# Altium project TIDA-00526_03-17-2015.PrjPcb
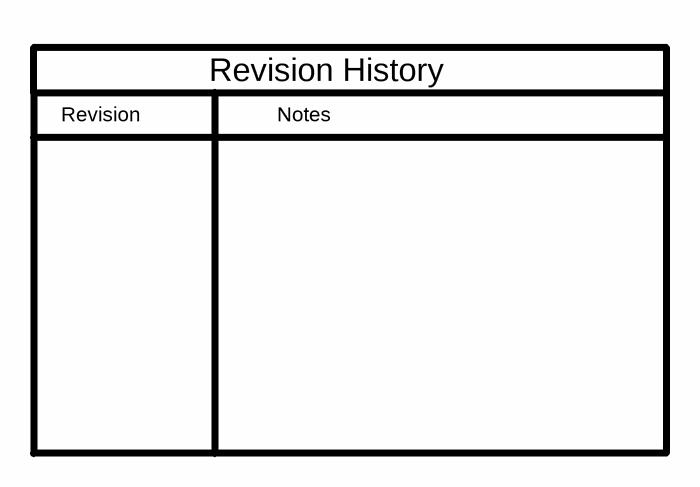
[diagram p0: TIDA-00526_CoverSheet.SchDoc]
TID: 00526; TechSupport: http://www.ti.com/support; SCH_Rev: E1; PRJ_Title: Using LDO for LED control & brightness matching; PRJ_Number: TIDA-00526; PRJ_Engineer: Antony Carvajales; PRJ_Customer: Public Release; PCB_Rev: E1; PCB_Layout: Antony Carvajales; EVM_Orderable: N/A; CopyrightYear: 2015
3 sheets, 39 parts. Net scope: global (net labels, ports and power ports of the same name join across sheets).
Board file: TIDA-00526_TID.PcbDoc
Sheets:
  TIDA-00526_CoverSheet.SchDoc
  TIDA-00526_BlankSheet.SchDoc
  TIDA-00526_Hardware.SchDoc

## Sheet TIDA-00526_CoverSheet.SchDoc
size 431 x 279 mm; Date: Not shown in title block; ApprovedBy: Not shown in title block; CheckedBy: Not shown in title block; Author: Not shown in title block; CompanyName: Not shown in title block; Engineer: Not shown in title block; Organization: Not shown in title block; Address1: Not shown in title block; Address2: Not shown in title block; Address3: Not shown in title block; Address4: Not shown in title block; DocumentNumber: 1; Revision: Use project parameter SCH_Rev; SheetNumber: 1; SheetTotal: 3; PageSetup: Record=PageOptions¦CenterHorizontal=True¦CenterVertical=True¦PrintScale=1.00¦XCorrection=1.00¦YCorrection=1.00¦PrintKind=0¦BorderSize=5000000¦LeftOffset=0¦BottomOffset=0¦Orientation=2¦PaperLength=1000¦PaperWidth=1000¦Scale=100¦PaperSource=15¦PrintQuality=600¦MediaType=1¦DitherType=10¦PaperKind=Letter¦PrintScaleMode=1

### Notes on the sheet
- Revision
- Notes
- Revision History

## Sheet TIDA-00526_BlankSheet.SchDoc
size 431 x 279 mm; Date: Not shown in title block; ApprovedBy: Not shown in title block; CheckedBy: Not shown in title block; Author: Not shown in title block; CompanyName: Texas Instruments; Engineer: Antony Carvajales; Organization: MDP_RF; Address1: Not shown in title block; Address2: Not shown in title block; Address3: Not shown in title block; Address4: Not shown in title block; DocumentNumber: 1; Revision: Use project parameter SCH_Rev; SheetNumber: 2; SheetTotal: 3; PageSetup: Record=PageOptions¦CenterHorizontal=True¦CenterVertical=True¦PrintScale=1.00¦XCorrection=1.00¦YCorrection=1.00¦PrintKind=0¦BorderSize=5000000¦LeftOffset=0¦BottomOffset=0¦Orientation=2¦PaperLength=1000¦PaperWidth=1000¦Scale=100¦PaperSource=15¦PrintQuality=-3¦MediaType=1¦DitherType=10¦PrintScaleMode=1¦PaperKind=Letter¦PaperIndex=1
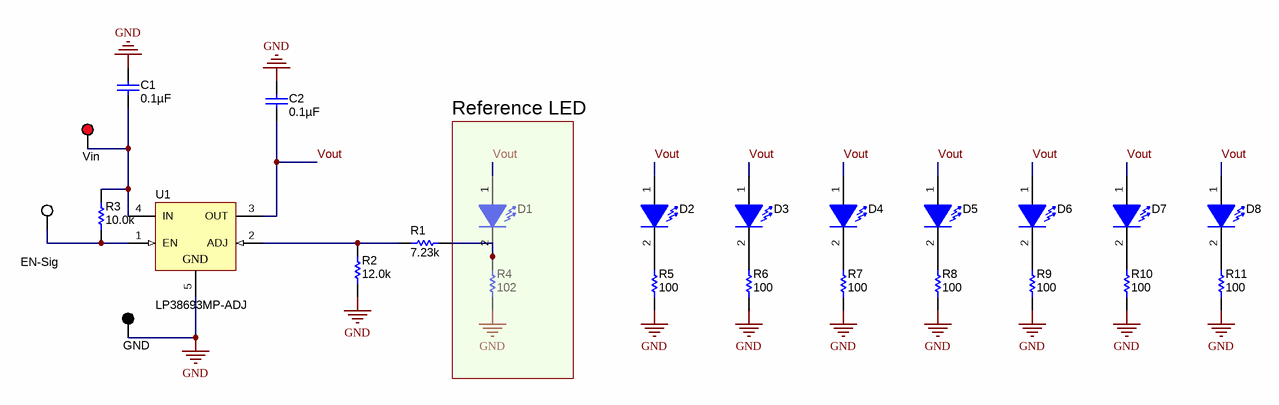
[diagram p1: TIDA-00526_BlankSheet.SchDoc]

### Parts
C1  ValueDisplayed: 0.1µF  [0805_HV]  (hidden comment: C0805C104K3RACTU)
C2  ValueDisplayed: 0.1µF  [0805_HV]  (hidden comment: C0805C104K3RACTU)
D1  C503D-WAN-CCBDB232  [HLMP-341_YELLOW]  (value not drawn)
D2  C503D-WAN-CCBDB232  [HLMP-341_YELLOW]  (value not drawn)
D3  LED, White, TH  [HLMP-341_YELLOW]  (value not drawn)
D4  C503D-WAN-CCBDB232  [HLMP-341_YELLOW]  (value not drawn)
D5  C503D-WAN-CCBDB232  [HLMP-341_YELLOW]  (value not drawn)
D6  C503D-WAN-CCBDB232  [HLMP-341_YELLOW]  (value not drawn)
D7  C503D-WAN-CCBDB232  [HLMP-341_YELLOW]  (value not drawn)
D8  C503D-WAN-CCBDB232  [HLMP-341_YELLOW]  (value not drawn)
EN-Sig  5002  [Keystone5002]  (value not drawn)
GND  5001  [Keystone5001]  (value not drawn)
R1  ValueDisplayed: 7.23k  [0603]  (hidden comment: RT0603DRE077K23L)
R2  ValueDisplayed: 12.0k  [0603]  (hidden comment: RC0603FR-0712KL)
R3  ValueDisplayed: 10.0k  [0603]  (hidden comment: CRCW060310K0FKEA)
R4  ValueDisplayed: 102  [0603]  (hidden comment: CRCW0603102RFKEA)
R5  ValueDisplayed: 100  [0603]  (hidden comment: RC0603FR-07100RL)
R6  ValueDisplayed: 100  [0603]  (hidden comment: RC0603FR-07100RL)
R7  ValueDisplayed: 100  [0603]  (hidden comment: RC0603FR-07100RL)
R8  ValueDisplayed: 100  [0603]  (hidden comment: RC0603FR-07100RL)
R9  ValueDisplayed: 100  [0603]  (hidden comment: RC0603FR-07100RL)
R10  ValueDisplayed: 100  [0603]  (hidden comment: RC0603FR-07100RL)
R11  ValueDisplayed: 100  [0603]  (hidden comment: RC0603FR-07100RL)
U1  LP38693MP-ADJ  [MP05A_N]
Vin  5000  [Keystone5000]  (value not drawn)

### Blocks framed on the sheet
Reference LED: D1 R4

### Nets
GND: C1.1 C2.1 GND.1 R2.1 R4.1 R5.1 R6.1 R7.1 R8.1 R9.1 R10.1 R11.1 U1.5(GND)
Vout: C2.2 D1.1(A) D2.1(A) D3.1(A) D4.1(A) D5.1(A) D6.1(A) D7.1(A) D8.1(A) U1.3(OUT)
NetC1_2: C1.2 R3.2 U1.4(IN) Vin.1
NetD1_2: D1.2(K) R1.2 R4.2
NetD2_2: D2.2(K) R5.2
NetD3_2: D3.2(K) R6.2
NetD4_2: D4.2(K) R7.2
NetD5_2: D5.2(K) R8.2
NetD6_2: D6.2(K) R9.2
NetD7_2: D7.2(K) R10.2
NetD8_2: D8.2(K) R11.2
NetEN-Sig_1: EN-Sig.1 R3.1 U1.1(EN)
NetR1_1: R1.1 R2.2 U1.2(ADJ)

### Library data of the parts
C1 C2 = C0805C104K3RACTU: CAP, CERM, 0.1 µF, 25 V, +/- 10%, X7R, 0805; Manufacturer: Kemet; Polarized: N; CompType: Capacitor; Value: 0.1uF; U/M: EA; Cap_F: 0.0000001; Tolerance_%: 10; ESR_ohm: 0.064; Value1: 0.064 ohm; VDC_V: 25; Value2: 25V; IRMS_A: 1.64; TaMin_C: -55; TaMax_C: 125; Cap_Case: 0805
D1 D2 D4 D5 D7 D8 = HLMP-3416: LED, White, TH; Manufacturer: CREE
D3 = HLMP-3416: Manufacturer: CREE; PartNumber: C503D-WAN-CCBDB232
D6 = HLMP-3416: LED, white, TH; Manufacturer: CREE
EN-Sig = 5002: Test Point, Miniature, White, TH; Manufacturer: Keystone; CompType: Test Point Loop; U/M: EA
GND = 5001: Test Point, Miniature, Black, TH; Manufacturer: Keystone; CompType: Test Point Loop; U/M: EA
R1 = RT0603DRE077K23L: RES, 7.23 k, 0.5%, 0.1 W, 0603; Manufacturer: Yageo America; CompType: Resistor; Value: 7.23k; Res_ohm: 7230; Value_Code: 7k23; Tolerance_%: 0.5; Power_W: 0.1; Value2: 0.1W; VDC_V: 75; TempCo: 50 ppm/C; EIA_Code: E192; U/M: EA
R2 = RC0603FR-0712KL: RES, 12.0 k, 1%, 0.1 W, 0603; Manufacturer: Yageo America; CompType: Resistor; Value: 12.0k; Res_ohm: 12000; Value_Code: 12k0; Tolerance_%: 1; Power_W: 0.1; Value2: 0.1W; VDC_V: 150; TempCo: 200 ppm/C; U/M: EA
R3 = CRCW060310K0FKEA: RES, 10.0 k, 1%, 0.1 W, 0603; Manufacturer: Vishay-Dale; CompType: Resistor; Value: 10.0k; Res_ohm: 10000; Value_Code: 10k0; Tolerance_%: 1; Power_W: 0.1; Value2: 0.1W; VDC_V: 75; TempCo: 100 ppm/C; EIA_Code: E96; U/M: EA
R4 = CRCW0603102RFKEA: RES, 102, 1%, 0.1 W, 0603; Manufacturer: Vishay-Dale; CompType: Resistor; Value: 102; Value_Code: 102R; Tolerance_%: 1; Power_W: 0.1; Value2: 0.1W; VDC_V: 75; TempCo: 100 ppm/C; EIA_Code: E96; U/M: EA
R5-R11 = RC0603FR-07100RL: RES, 100, 1%, 0.1 W, 0603; Manufacturer: Yageo America; CompType: Resistor; Value: 100; Value_Code: 100R; Tolerance_%: 1; Power_W: 0.1; Value2: 0.1W; VDC_V: 150; TempCo: 200 ppm/C; EIA_Code: E96; U/M: EA
U1 = LP38693MP-ADJ: 500mA Low Dropout CMOS Linear Regulators, 5-pin SOT-223; Manufacturer: Texas Instruments; PackageTopMarking: XYTT*LJUB; PowerWise: Y; CompType: LDO IC
Vin = 5000: Test Point, Miniature, Red, TH; Manufacturer: Keystone; CompType: Test Point Loop; U/M: EA

## Sheet TIDA-00526_Hardware.SchDoc
size 431 x 279 mm; Date: Not shown in title block; ApprovedBy: Not shown in title block; CheckedBy: Not shown in title block; Author: Not shown in title block; CompanyName: Not shown in title block; Engineer: Not shown in title block; Organization: Not shown in title block; Address1: Not shown in title block; Address2: Not shown in title block; Address3: Not shown in title block; Address4: Not shown in title block; DocumentNumber: 1; Revision: Use project parameter SCH_Rev; SheetNumber: 3; SheetTotal: 3; PageSetup: Record=PageOptions¦CenterHorizontal=True¦CenterVertical=True¦PrintScale=1.00¦XCorrection=1.00¦YCorrection=1.00¦PrintKind=0¦BorderSize=5000000¦LeftOffset=0¦BottomOffset=0¦Orientation=2¦PaperLength=1000¦PaperWidth=1000¦Scale=100¦PaperSource=15¦PrintQuality=600¦MediaType=1¦DitherType=10¦PaperKind=Letter¦PrintScaleMode=1
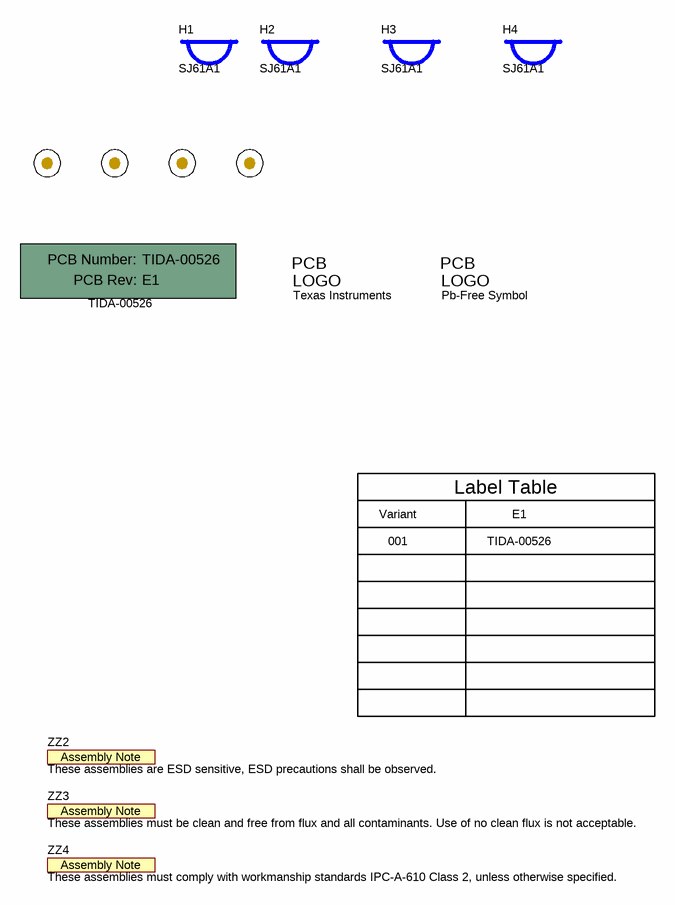
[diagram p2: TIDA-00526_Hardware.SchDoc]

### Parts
!PCB  TIDA-00526  (mechanical)
FID1  Fiducial  [Fiducial10-20]  (value not drawn)
FID2  Fiducial  [Fiducial10-20]  (value not drawn)
FID3  Fiducial  [Fiducial10-20]  (value not drawn)
FID4  Fiducial  [Fiducial10-20]  (value not drawn)
H1  SJ61A1  [Bumpon_SJ61A1]
H2  SJ61A1  [Bumpon_SJ61A1]
H3  SJ61A1  [Bumpon_SJ61A1]
H4  SJ61A1  [Bumpon_SJ61A1]
Logo1  Texas Instruments  [TI_Stacked_SolderMask_Small]  (no BOM)
Logo2  Pb-Free Symbol  [Pb-Free_Overlay_Small]  (no BOM)
ZZ2  These assemblies are ESD sensitive, ESD precautions shall be observed.  [AssemblyNote]  (no BOM)
ZZ3  These assemblies must be clean and free from flux and all contaminants. Use of no clean flux is not acceptable.  [AssemblyNote]  (no BOM)
ZZ4  These assemblies must comply with workmanship standards IPC-A-610 Class 2, unless otherwise specified.  [AssemblyNote]  (no BOM)

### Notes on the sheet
- Variant
- Label Table
- E1
- 001
- TIDA-00526

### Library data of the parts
!PCB = PCB: Printed Circuit Board; Manufacturer: Any; SymbolCreator: a0412235
FID1-FID4 = Fiducial: Fiducial mark.  There is nothing to buy or mount.; SymbolCreator: codlsc
H1-H4 = SJ61A1: Bumpon, Cylindrical, 0.312 X 0.200, Black; Manufacturer: 3M; SymbolCreator: a0412235
Logo1 = TI_Logo: Texas Instrument Corporate Signature; SymbolCreator: codlsc
Logo2 = Pb-Free: SymbolCreator: a0412235
ZZ2-ZZ4 = AssemblyNote: SymbolCreator: codlsc

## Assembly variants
001: not fitted R3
